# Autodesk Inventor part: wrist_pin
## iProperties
Created: 2001-11
Part Number: wrist_pin
Document SubType Name: Modeling
Designer: hassen
Density: 1 g/cm^3
Control State: 0
Master: False
Checked Out: False
Shininess: 64.0
Length Units: 11269
Angle Units: 11279
Time Units: 11290
Mass Units: 11283
Length Display Precision: 3
Angle Display Precision: 2
Density: 0.0
Volumn: 0.0
Area: 0.0
PropertySet Name: Model Information
Author: hassen
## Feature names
1. Extrusion1
2. Hole1
3. Chamfer1
